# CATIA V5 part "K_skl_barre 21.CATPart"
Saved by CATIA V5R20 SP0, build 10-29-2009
Part number: skl_barre 21
Publications: "longueur axe pivot", "liaison 10/21", "liaison 21/28", "liaison 21/74 sur 21", "Plan.00", "Droite.1", "Droite.2", "Droite.3", "Droite.4", "Droite.5"
Bounding box of the stored display mesh (mm): x 0 to 150, y -910 to 150, z 445 to 500
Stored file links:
  G:\Khaled_CFAO_2011\SIL\SIL_GR2\mdardier\Khaled\CAD_ThinkMOTION\K_skl_barre 21.CATPart
  G:\Khaled_CFAO_2011\SIL\SIL_GR2\mdardier\Khaled\CAD_ThinkMOTION\K_skl_ass_tandem.CATProduct
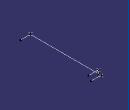
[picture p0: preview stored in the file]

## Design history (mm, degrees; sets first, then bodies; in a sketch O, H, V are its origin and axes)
External parameters (linked from other documents)
  `External.longueur axe pivot` = 150 mm
Set1
  Point1 "liaison 10/21": linked copy from another document
  Point2 "liaison 21/28": linked copy from another document
  Point3 "liaison 21/74 sur 21": linked copy from another document
  Plane1 "Plan.00": linked copy from another document
Set2
  Line1: type PtPt, FirstPoint Point1, SecondPoint Point2
  Line2: type Angle, LineFirstUpto Line1, RefPoint Point3, Start 0, End 0, Angle 90
  Line3: type Normal, RefPoint Point1, RefSkin Plane1, Start 0, End 150 {= `External.longueur axe pivot`}
  Line4: type Normal, RefPoint Point3, RefSkin Plane1, Start 0, End 150 {= `External.longueur axe pivot`}
  Line5: type Normal, RefPoint Point2, RefSkin Plane1, Start 0, End 150 {= `External.longueur axe pivot`}
Body1 (main body)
